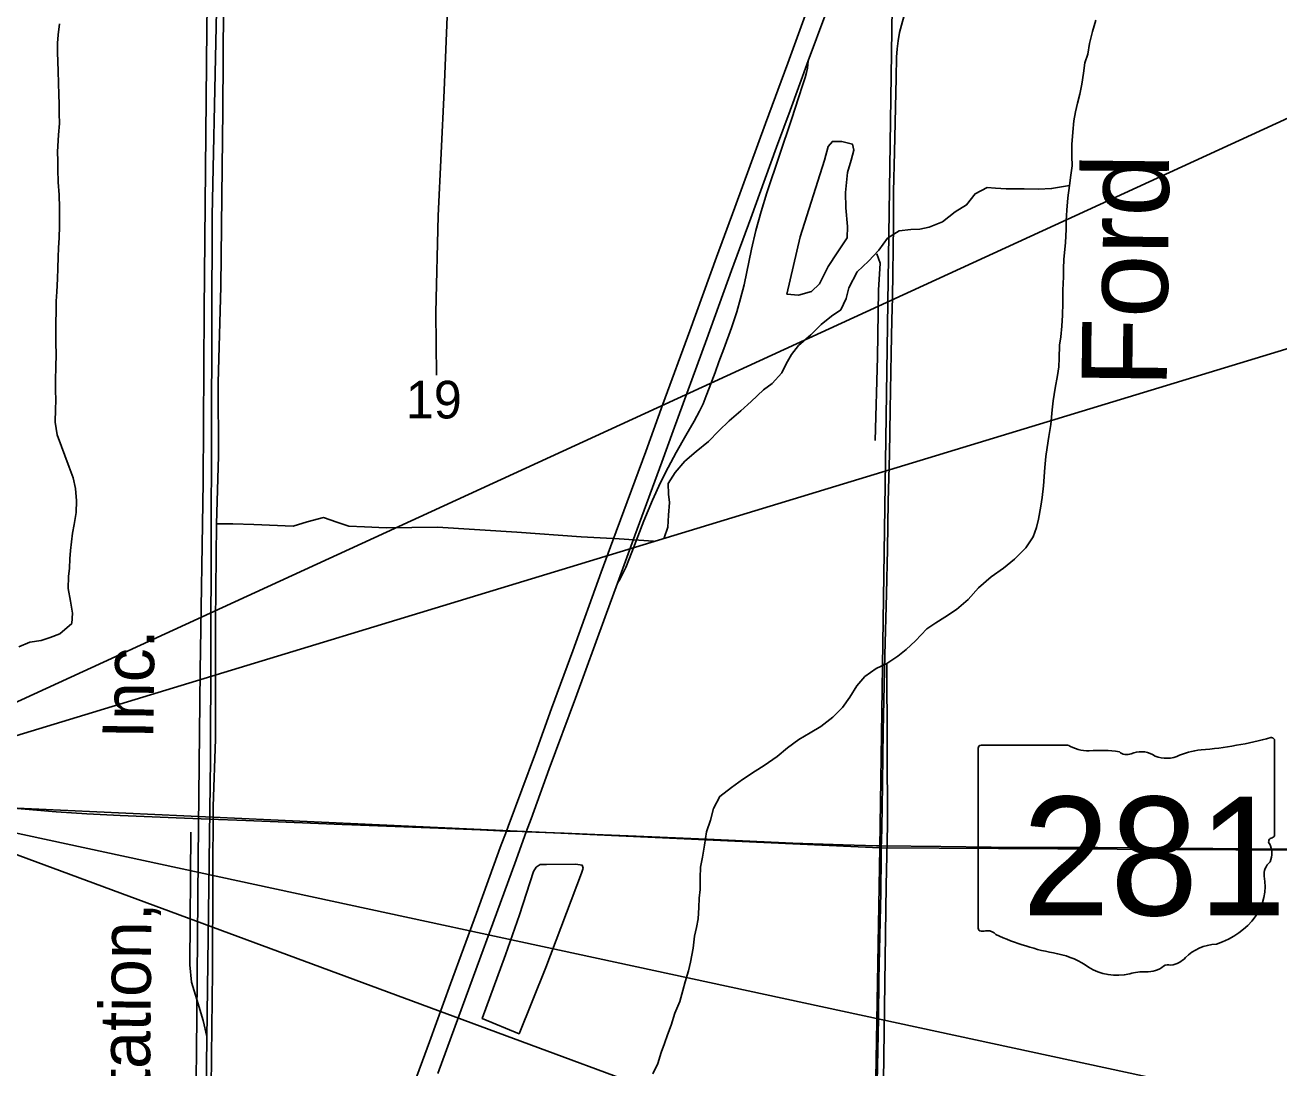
# Model space of a CAD drawing. Extents: x 0 to 39.4, y 0 to 22.
# Drawn here: x 5.438 to 6.833, y 17.096 to 18.256 of the extents above; entities that cross this region are included whole.
import ezdxf

# ---------------------------------------------------------------- set-up
doc = ezdxf.new("R2010")
doc.units = 0
for name, color, linetype in [('GM_X_Interchange_Ramps', 7, 'Continuous'), ('GM_X_Interstate_Route', 7, 'Continuous'), ('GM_X_Minor_Lake', 7, 'Continuous'), ('GM_X_Minor_River', 7, 'Continuous'), ('GM_X_Minor_River_Text', 7, 'Continuous'), ('GM_X_Rail_Line', 7, 'Continuous'), ('GM_X_Rail_Line_Text', 7, 'Continuous'), ('GM_X_Section', 7, 'Continuous'), ('GM_X_Section_Text', 7, 'Continuous'), ('GM_X_State_Route', 7, 'Continuous'), ('GM_X_State_Shield', 7, 'Continuous'), ('GM_X_Township_Road', 7, 'Continuous'), ('SH_Data', 7, 'Continuous')]:
    doc.layers.add(name, color=color, linetype=linetype)

msp = doc.modelspace()

# ---------------------------------------------------------------- linework, layer by layer
at = {"layer": 'GM_X_Interchange_Ramps'}
msp.add_lwpolyline([(6.0968, 17.635), (6.0997, 17.6396), (6.1035, 17.6471), (6.1059, 17.6524), (6.1127, 17.6696), (6.1262, 17.7043), (6.1358, 17.7273), (6.1448, 17.7471), (6.1531, 17.7638), (6.1619, 17.7803), (6.1728, 17.7991), (6.1822, 17.8152), (6.1881, 17.8262), (6.192, 17.8346), (6.1956, 17.8433), (6.1987, 17.852), (6.2055, 17.8694), (6.2097, 17.8811), (6.215, 17.8957), (6.2236, 17.9191), (6.2294, 17.9368), (6.2338, 17.9517), (6.2376, 17.9668), (6.2458, 18.0064), (6.2508, 18.0275), (6.2565, 18.0485), (6.2629, 18.0693), (6.2908, 18.1518), (6.2983, 18.1751), (6.3031, 18.1897), (6.3056, 18.1977), (6.307, 18.2032), (6.308, 18.2081), (6.3091, 18.2161)], dxfattribs=at)
at = {"layer": 'GM_X_Interstate_Route'}
for points in [[(5.8682, 17.0722), (5.8875, 17.1247), (5.911, 17.189), (5.94, 17.2677), (5.9664, 17.3408), (5.9733, 17.3591), (5.9751, 17.3641), (6.0055, 17.4457), (6.0234, 17.4954), (6.0471, 17.5596), (6.0786, 17.6473), (6.0915, 17.6823), (6.1284, 17.7814), (6.1474, 17.834), (6.1772, 17.9158), (6.2069, 17.9976), (6.2274, 18.053), (6.2615, 18.1464), (6.2862, 18.2135), (6.316, 18.2953)], [(5.897, 17.0895), (5.9162, 17.1421), (5.9824, 17.3231), (5.9953, 17.3583), (6.0006, 17.3727), (6.0206, 17.4282), (6.05, 17.5069), (6.0831, 17.5974), (6.0968, 17.635), (6.116, 17.6879), (6.1461, 17.7696), (6.1588, 17.8046), (6.1961, 17.9069), (6.2236, 17.9828), (6.2451, 18.0412), (6.2609, 18.085), (6.2738, 18.1201), (6.289, 18.1608), (6.3091, 18.2161), (6.3284, 18.2689)]]:
    msp.add_lwpolyline(points, dxfattribs=at)
at = {"layer": 'GM_X_Minor_Lake'}
for p, q in [((6.2999, 18.0201), (6.2853, 17.9563)), ((5.9877, 17.2658), (5.972, 17.2214))]:
    msp.add_line(p, q, dxfattribs=at)
for points in [[(6.2853, 17.9563), (6.2982, 17.9552), (6.3126, 17.9593), (6.3214, 17.968), (6.3313, 17.9873), (6.3412, 18.0025), (6.3523, 18.0192), (6.3527, 18.0317), (6.3509, 18.0526), (6.3505, 18.0697), (6.3525, 18.0918), (6.3567, 18.1054), (6.3598, 18.1168), (6.3583, 18.1233), (6.3462, 18.1263), (6.3359, 18.1264), (6.3313, 18.1207), (6.3271, 18.1055), (6.2999, 18.0201)], [(5.972, 17.2214), (5.9463, 17.1504), (5.9873, 17.1336), (6.0171, 17.2072), (6.0568, 17.3123), (6.0584, 17.318), (6.0576, 17.321), (6.0504, 17.3222), (6.0178, 17.3219), (6.0106, 17.3219), (6.0064, 17.3189), (6.0034, 17.314), (5.9877, 17.2658)]]:
    msp.add_lwpolyline(points, dxfattribs=at)
at = {"layer": 'GM_X_Minor_River'}
for points in [[(5.9174, 18.8482), (5.916, 18.7832), (5.9166, 18.7114), (5.9171, 18.6324), (5.9124, 18.6024), (5.9131, 18.5679), (5.9148, 18.4938), (5.9138, 18.4315), (5.9113, 18.351), (5.9085, 18.3244), (5.908, 18.2837), (5.9039, 18.1831), (5.8974, 18.0437), (5.8945, 17.9362), (5.8954, 17.8663)], [(5.6416, 18.3738), (5.6397, 18.2519), (5.6368, 17.9388), (5.6359, 17.7474), (5.6326, 17.5373), (5.6301, 17.3295), (5.6288, 17.1521), (5.6277, 17.0461), (5.6263, 16.8296), (5.6266, 16.6901), (5.626, 16.6134), (5.6259, 16.4588), (5.6242, 16.3714), (5.6213, 16.1704), (5.6181, 16.0048), (5.6172, 15.8411), (5.614, 15.6538), (5.6138, 15.5695), (5.6113, 15.4942), (5.6102, 15.3905), (5.6089, 15.3442), (5.6082, 15.2177), (5.6092, 15.1099)], [(5.6597, 18.3445), (5.6584, 18.2769), (5.6576, 18.161), (5.6566, 18.0657), (5.6555, 17.965), (5.6525, 17.8579), (5.653, 17.7762), (5.6505, 17.701), (5.6494, 17.592), (5.6494, 17.4613), (5.6469, 17.3864), (5.6467, 17.3078), (5.646, 17.2026), (5.645, 17.1091), (5.6439, 17.0001), (5.6428, 16.899), (5.6424, 16.7589), (5.6428, 16.6559)], [(6.6289, 18.2615), (6.6254, 18.2486), (6.6219, 18.2353), (6.62, 18.2236), (6.6169, 18.2137), (6.6154, 18.2023), (6.6135, 18.1901), (6.6111, 18.1791), (6.6085, 18.1689), (6.6062, 18.1594), (6.6046, 18.1495), (6.6034, 18.1366), (6.6022, 18.1229), (6.6022, 18.11), (6.6026, 18.0994), (6.601, 18.0888), (6.5995, 18.0774), (6.5979, 18.0637), (6.5967, 18.05), (6.5959, 18.0379), (6.5959, 18.0284), (6.5951, 18.0139), (6.5935, 17.9949), (6.5931, 17.9851), (6.5931, 17.9756), (6.5923, 17.9608), (6.5922, 17.9463), (6.5918, 17.933), (6.591, 17.9209), (6.5902, 17.9091), (6.5887, 17.8996), (6.5882, 17.8852), (6.5878, 17.8757), (6.5863, 17.8658), (6.5836, 17.8518), (6.5816, 17.8377), (6.5805, 17.8278), (6.5789, 17.8115), (6.5766, 17.7982), (6.575, 17.7857), (6.5735, 17.7758), (6.5723, 17.7637), (6.5707, 17.7431), (6.5692, 17.7302), (6.5676, 17.7207), (6.5653, 17.7063), (6.563, 17.6968), (6.5592, 17.6866), (6.5512, 17.6741), (6.5386, 17.6616), (6.5264, 17.6517), (6.5124, 17.6419), (6.4983, 17.6298), (6.4869, 17.6169), (6.4739, 17.6055), (6.461, 17.5972), (6.4508, 17.5908), (6.4409, 17.584), (6.4283, 17.5707), (6.418, 17.5612), (6.4085, 17.5537), (6.3964, 17.5457), (6.3846, 17.5401), (6.372, 17.531), (6.3629, 17.5207), (6.3553, 17.5082), (6.3473, 17.4965), (6.3362, 17.4859), (6.3229, 17.4753), (6.3111, 17.4685), (6.2986, 17.4609), (6.2861, 17.4518), (6.2743, 17.442)], [(5.4758, 18.2573), (5.4746, 18.2451), (5.4738, 18.2356), (5.4738, 18.2257), (5.4742, 18.2151), (5.4745, 18.2049), (5.4748, 18.1908), (5.4752, 18.179), (5.4755, 18.1676), (5.4755, 18.1574), (5.4758, 18.1463), (5.4747, 18.1338), (5.4739, 18.1148), (5.4742, 18.1049), (5.4742, 18.0951), (5.4745, 18.081), (5.4756, 18.067), (5.4759, 18.0525), (5.4759, 18.032), (5.4755, 18.0191), (5.475, 18.0081), (5.4746, 17.9978), (5.4742, 17.9853), (5.4738, 17.9735), (5.473, 17.9591), (5.4722, 17.9488), (5.4722, 17.9363), (5.4718, 17.9256), (5.4717, 17.9021), (5.4724, 17.8896), (5.472, 17.8751), (5.4716, 17.8611), (5.4715, 17.85), (5.4719, 17.8383), (5.4715, 17.8284), (5.471, 17.814), (5.4733, 17.7999), (5.4782, 17.787), (5.4819, 17.7771), (5.4868, 17.7641), (5.491, 17.752), (5.4936, 17.7402), (5.4947, 17.7265), (5.4946, 17.7136), (5.4923, 17.7003), (5.4904, 17.6904), (5.4881, 17.6714), (5.4873, 17.662), (5.4869, 17.6517), (5.4861, 17.6422), (5.4857, 17.6289), (5.4883, 17.6148), (5.4905, 17.6015), (5.4897, 17.5901), (5.4764, 17.5784), (5.4654, 17.5743), (5.4555, 17.5712), (5.443, 17.5694), (5.4308, 17.5641)], [(6.5995, 18.0774), (6.5797, 18.074), (6.5653, 18.0733), (6.5494, 18.0737), (6.5292, 18.0738), (6.5175, 18.0746), (6.508, 18.075), (6.4947, 18.0682), (6.4852, 18.0557), (6.4726, 18.0481), (6.4582, 18.0371), (6.4434, 18.0311), (6.4331, 18.0288), (6.4233, 18.0285), (6.41, 18.027), (6.397, 18.0187), (6.3875, 18.0054), (6.3761, 17.9933), (6.3635, 17.9812), (6.354, 17.9634), (6.3513, 17.9516), (6.3452, 17.9391), (6.3349, 17.9319), (6.3235, 17.9228), (6.3117, 17.9114), (6.298, 17.8993), (6.2904, 17.8895), (6.2843, 17.8788), (6.2797, 17.869), (6.2687, 17.8572), (6.2592, 17.85), (6.2455, 17.8372), (6.2341, 17.8266), (6.2211, 17.8156), (6.2097, 17.8046), (6.1979, 17.7925), (6.1842, 17.7815), (6.1717, 17.7705), (6.161, 17.758), (6.153, 17.7459), (6.1534, 17.7341), (6.1545, 17.7246), (6.1537, 17.7105), (6.1529, 17.6973), (6.1487, 17.6855)], [(6.3852, 18.0013), (6.389, 17.991), (6.387, 17.961), (6.386, 17.8865), (6.3835, 17.7935)], [(6.1369, 17.6817), (6.0986, 17.6841), (6.0565, 17.6865), (5.9848, 17.6917), (5.8964, 17.6972), (5.8395, 17.6966), (5.8152, 17.6975), (5.7977, 17.6983), (5.7845, 17.7029), (5.7697, 17.7079), (5.7515, 17.703), (5.7358, 17.6984), (5.6923, 17.7001), (5.6687, 17.7009), (5.6505, 17.701)], [(6.3964, 17.5457), (6.3973, 17.3656), (6.3956, 17.2984), (6.3922, 17.0541), (6.3894, 16.8623), (6.3882, 16.7111), (6.3859, 16.6063), (6.3821, 16.4558), (6.3784, 16.3601), (6.359, 16.34), (6.3585, 16.171), (6.3562, 16.0407), (6.3531, 15.8883), (6.3459, 15.7702), (6.3414, 15.6665), (6.3377, 15.5822), (6.334, 15.4937), (6.3295, 15.3797)], [(6.2743, 17.442), (6.2598, 17.4322), (6.2499, 17.4257), (6.2359, 17.4163), (6.2237, 17.4076), (6.2108, 17.3977), (6.2035, 17.3841), (6.2004, 17.3712), (6.1959, 17.3583), (6.1935, 17.3434), (6.1912, 17.3302), (6.1893, 17.3188), (6.1889, 17.307), (6.1888, 17.2941), (6.1877, 17.2846), (6.1872, 17.2739), (6.1865, 17.2614), (6.1845, 17.2519), (6.1826, 17.242), (6.181, 17.2288), (6.178, 17.2132), (6.1757, 17.2037), (6.1722, 17.1912), (6.1695, 17.1817), (6.1661, 17.1695), (6.1607, 17.1566), (6.1565, 17.143), (6.1523, 17.1323), (6.1489, 17.1229), (6.1454, 17.1126), (6.1416, 17.1005), (6.1362, 17.0891)]]:
    msp.add_lwpolyline(points, dxfattribs=at)
at = {"layer": 'GM_X_Rail_Line'}
for points in [[(5.6115, 14.1), (5.6226, 15.3413), (5.6228, 15.3801), (5.635, 16.7601), (5.6441, 17.4388), (5.6457, 18.044), (5.6539, 18.4301), (5.6611, 19.3588), (5.6728, 20.3992), (5.6755, 20.8483), (5.6758, 20.9)], [(5.6399, 17.1306), (5.6357, 17.1482), (5.6286, 17.1717), (5.623, 17.1909), (5.621, 17.2104), (5.622, 17.358)]]:
    msp.add_lwpolyline(points, dxfattribs=at)
at = {"layer": 'GM_X_Section'}
for points in [[(5.3956, 18.3552), (6.4032, 18.3261), (6.3887, 17.3403), (5.3882, 17.3864)], [(7.4046, 18.3152), (7.3784, 17.3348), (6.3887, 17.3403), (6.4032, 18.3261)], [(5.3882, 17.3864), (6.3887, 17.3403), (6.3716, 16.3557), (5.8324, 16.3859), (5.386, 16.3879)], [(7.3784, 17.3348), (7.3732, 16.344), (6.3716, 16.3557), (6.3887, 17.3403)]]:
    msp.add_lwpolyline(points, close=True, dxfattribs=at)
at = {"layer": 'GM_X_State_Route'}
for points in [[(5.3942, 17.3868), (5.4163, 17.3852), (5.4721, 17.3805), (5.5062, 17.3781), (5.5435, 17.3763), (5.6056, 17.374), (5.6429, 17.3725), (5.6832, 17.3708), (5.764, 17.3676), (5.7905, 17.3665)], [(5.7905, 17.3665), (5.8013, 17.3661), (5.8975, 17.3622), (5.9441, 17.3603), (5.9733, 17.3591), (5.9907, 17.3585), (5.9953, 17.3583), (6.0373, 17.3566), (6.0714, 17.3553), (6.1087, 17.3537), (6.1614, 17.3514), (6.1956, 17.35), (6.1966, 17.35)], [(6.1966, 17.35), (6.236, 17.3482), (6.2919, 17.3457), (6.3478, 17.3438), (6.3851, 17.3426), (6.3903, 17.3425), (6.4566, 17.3418), (6.5125, 17.3413), (6.5716, 17.3408), (6.6307, 17.3407), (6.6742, 17.3403), (6.8016, 17.3392), (6.898, 17.3386)]]:
    msp.add_lwpolyline(points, dxfattribs=at)
at = {"layer": 'GM_X_State_Shield'}
for p, q in [((6.598, 17.4548), (6.5014, 17.4548)), ((6.8278, 17.3551), (6.8278, 17.4598)), ((6.4982, 17.4514), (6.4982, 17.2512)), ((6.8278, 17.3551), (6.8278, 17.3551))]:
    msp.add_line(p, q, dxfattribs=at)
for centre, major_axis, start_param, end_param in [((6.502, 17.4518), (0.00382, 0), 1.712693, 3.28349), ((6.621, 17.478), (0.037, 0), 4.042523, 4.731795), ((6.7104, 17.7276), (0.3495, 0), 4.814394, 5.042369), ((6.8241, 17.4602), (0.00367, 0), 6.141152, 7.989035), ((6.6332, 17.3425), (0.133, 0), 1.404758, 1.657858), ((6.6634, 17.4528), (0.0107, 0), 3.836095, 5.185415), ((6.6791, 17.4297), (0.0222, 0), 0.950623, 2.079405), ((6.7078, 17.4614), (0.0267, 0), 4.081561, 5.145723), ((6.755, 17.3937), (0.0703, 0), 1.699011, 2.107814), ((6.8239, 17.3547), (0.00393, 0), 5.05454, 6.418171), ((6.8269, 17.3474), (0.00568, 0), 1.883978, 3.671073), ((6.7908, 17.3342), (0.0341, 0), 5.934695, 6.695948), ((6.8409, 17.3113), (0.0248, 0), 2.387724, 3.262537), ((6.73, 17.298), (0.0874, 0), 5.101752, 6.440018), ((6.502, 17.2508), (0.00385, 0), 3.00124, 4.508301), ((6.5026, 17.2713), (0.0294, 0), 4.665946, 4.897461), ((6.5086, 17.2397), (0.0106, 0), 0.519207, 1.627899), ((6.6424, 17.4195), (0.2524, 0), 4.195997, 4.488961), ((6.7668, 17.1951), (0.0479, 0), 1.647645, 2.488434), ((6.5672, 17.1613), (0.079, 0), 0.823519, 1.323587), ((6.7062, 17.2318), (0.0282, 0), 4.937069, 5.64225), ((6.6526, 17.2387), (0.0501, 0), 4.026481, 4.996735), ((6.6816, 17.1695), (0.0412, 0), 1.495662, 1.94098), ((6.6852, 17.2237), (0.0267, 0), 4.691044, 5.507374), ((6.7094, 17.2043), (0.00752, 0), 1.147584, 2.315152)]:
    msp.add_ellipse(centre, major_axis=major_axis, ratio=0.8, start_param=start_param, end_param=end_param, dxfattribs=at)
at = {"layer": 'GM_X_Township_Road'}
for points in [[(6.4068, 18.197), (6.4073, 18.22), (6.4079, 18.2293), (6.409, 18.2385), (6.4107, 18.2477), (6.4137, 18.2598), (6.4247, 18.2986), (6.4287, 18.3137), (6.431, 18.3224)], [(6.3903, 17.3425), (6.3904, 17.3465), (6.3911, 17.3838), (6.3923, 17.4708), (6.3944, 17.5548), (6.3959, 17.6231), (6.397, 17.6729), (6.3981, 17.7257), (6.3993, 17.7786), (6.4, 17.8283), (6.4013, 17.8905), (6.4021, 17.9278), (6.4027, 17.9526), (6.4037, 18.0335), (6.4039, 18.0708), (6.4051, 18.1143), (6.4068, 18.197)], [(6.374, 16.3582), (6.374, 16.3611), (6.374, 16.3798), (6.3755, 16.4513), (6.3769, 16.5228), (6.3799, 16.616), (6.3807, 16.644), (6.3817, 16.7155), (6.3819, 16.7652), (6.3825, 16.8336), (6.3833, 16.8833), (6.384, 16.9579), (6.3844, 17.0263), (6.3857, 17.0792), (6.387, 17.1507), (6.3876, 17.1942), (6.3896, 17.2906), (6.3901, 17.331), (6.3903, 17.3425)]]:
    msp.add_lwpolyline(points, dxfattribs=at)
at = {"layer": 'SH_Data'}
for points in [[(9.4615, 18.6937), (5.1869, 17.3921), (9.4615, 19.3557)], [(9.482, 15.8329), (5.273, 17.39), (9.482, 16.4829)]]:
    msp.add_lwpolyline(points, close=True, dxfattribs=at)

# ---------------------------------------------------------------- texts
at = {"layer": 'GM_X_Minor_River_Text'}
msp.add_text('Ford', height=0.09475, rotation=89.3922, dxfattribs=at).set_placement((6.7078, 17.8522))
at = {"layer": 'GM_X_Rail_Line_Text'}
for s, height, rotation, p in [('Inc.', 0.05663, 89.3263, (5.5803, 17.4613)), ('Transportation,', 0.056629, 89.5032, (5.5739, 16.7703))]:
    msp.add_text(s, height=height, rotation=rotation, dxfattribs=at).set_placement(p)
at = {"layer": 'GM_X_Section_Text'}
msp.add_text('19', height=0.04186, rotation=0, dxfattribs=at).set_placement((5.8613, 17.8182))
at = {"layer": 'GM_X_State_Shield'}
msp.add_text('281', height=0.13184, dxfattribs=at).set_placement((6.5468, 17.2654))

doc.saveas('drawing.dxf')
